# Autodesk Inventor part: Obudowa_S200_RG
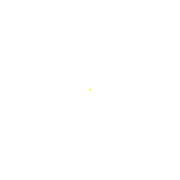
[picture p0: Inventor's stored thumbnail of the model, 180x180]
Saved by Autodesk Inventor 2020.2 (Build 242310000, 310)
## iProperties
Created: 2015-02
Part Number: Obudowa_S200_RG
Material: Ogólny
Document SubType Name: Modeling
Designer: F.Stasiak
Density: 1 g/cm^3
Appearance: Domyślna
Catalog Web Link: www.expertbooks.pl
Manager: www.cadconsulting.pl
Company: Fabian Stasiak CAD Consulting
Author: F.Stasiak
Subject: Zbiór ćwiczeń. Autodesk Inventor 2020. Kurs Professional
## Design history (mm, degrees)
node "Położenie przewężki 1_PZ:1"
